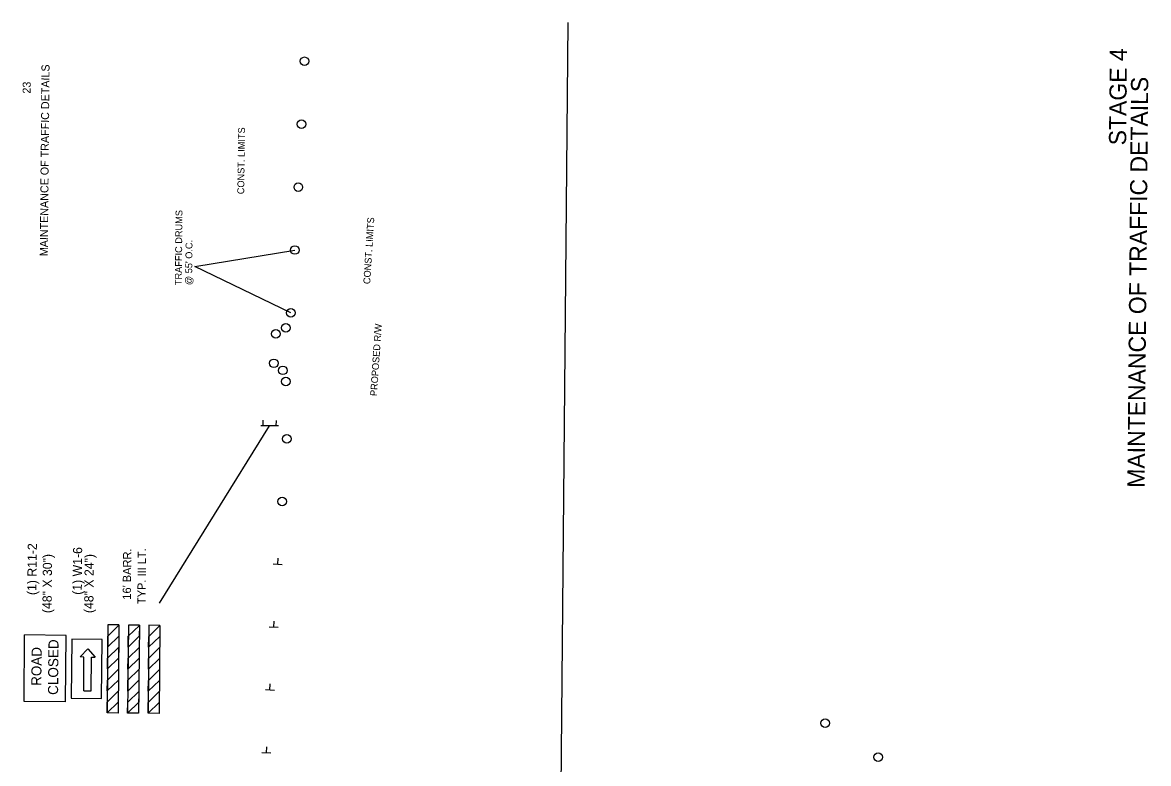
# Model space of a CAD drawing. Extents: x 1770269 to 1771406, y 724066 to 730989.
# Drawn here: x 1770316 to 1771298, y 730342 to 730989 of the extents above; entities that cross this region are included whole.
import ezdxf

# ---------------------------------------------------------------- set-up
doc = ezdxf.new("R2010")
doc.units = 0
for name, color, linetype in [('Default', 7, 'Continuous'), ('R_Border', 7, 'Continuous'), ('R_Border Notes', 7, 'Continuous'), ('R_Border PE', 7, 'Continuous'), ('R_Dimension', 7, 'Continuous'), ('R_MOT', 7, 'Continuous'), ('R_ROW Annot', 7, 'Continuous')]:
    doc.layers.add(name, color=color, linetype=linetype)

msp = doc.modelspace()

# ---------------------------------------------------------------- linework, layer by layer
at = {"layer": 'Default'}
for p, q in [((1770538.66, 730515.52), (1770539, 730520.85)), ((1770542.54, 730515.16), (1770534.73, 730515.66)), ((1770538.98, 730460.3), (1770531.17, 730460.75)), ((1770535.11, 730460.64), (1770535.42, 730465.97)), ((1770531.81, 730405.74), (1770532.1, 730411.07)), ((1770535.69, 730405.41), (1770527.88, 730405.83)), ((1770532.66, 730350.51), (1770524.85, 730350.9)), ((1770528.78, 730350.82), (1770529.05, 730356.15))]:
    msp.add_line(p, q, dxfattribs=at)
at = {"layer": 'R_Border Notes'}
msp.add_line((1770791.68, 730988.54), (1770777.32, 729407.71), dxfattribs=at)
at = {"layer": 'R_Border PE'}
msp.add_line((1770435.3, 730481.7), (1770531.55, 730636.47), dxfattribs=at)
at = {"layer": 'R_Dimension'}
msp.add_lwpolyline([(1770550.07, 730735.01), (1770466.33, 730775.45), (1770553.46, 730789.9)], dxfattribs=at)
at = {"layer": 'R_MOT'}
for p, q in [((1770539.34, 730636.42), (1770523.76, 730636.53)), ((1770525.88, 730636.51), (1770525.92, 730641.23)), ((1770537.37, 730636.43), (1770537.4, 730641.15)), ((1770390.38, 730462.64), (1770389.68, 730385.76)), ((1770400.03, 730462.55), (1770390.38, 730462.64)), ((1770400.03, 730462.55), (1770390.38, 730462.64)), ((1770400.03, 730462.55), (1770399.34, 730385.68)), ((1770408.28, 730462.47), (1770407.58, 730385.6)), ((1770417.9, 730462.39), (1770408.28, 730462.47)), ((1770417.9, 730462.39), (1770408.28, 730462.47)), ((1770417.9, 730462.39), (1770417.2, 730385.51)), ((1770426.11, 730462.31), (1770425.41, 730385.44)), ((1770435.73, 730462.22), (1770426.11, 730462.31)), ((1770435.73, 730462.22), (1770426.11, 730462.31)), ((1770435.73, 730462.22), (1770435.04, 730385.35)), ((1770317.21, 730395.88), (1770317.74, 730453.84)), ((1770353.94, 730453.51), (1770317.74, 730453.84)), ((1770353.42, 730395.55), (1770353.94, 730453.51)), ((1770366.27, 730434.61), (1770372.88, 730441.73)), ((1770372.88, 730441.73), (1770379.36, 730434.49)), ((1770369.54, 730434.58), (1770366.27, 730434.61)), ((1770369.27, 730405.19), (1770369.54, 730434.58)), ((1770375.82, 730405.13), (1770376.08, 730434.52)), ((1770376.08, 730434.52), (1770379.36, 730434.49)), ((1770369.27, 730405.19), (1770375.82, 730405.13)), ((1770353.42, 730395.55), (1770317.21, 730395.88)), ((1770399.34, 730385.68), (1770389.68, 730385.76)), ((1770399.31, 730385.73), (1770399.25, 730385.68)), ((1770417.2, 730385.51), (1770407.58, 730385.6)), ((1770417.2, 730385.51), (1770407.58, 730385.6)), ((1770435.04, 730385.35), (1770425.41, 730385.44))]:
    msp.add_line(p, q, dxfattribs=at)
for points in [[(1770390.21, 730443.39), (1770390.32, 730452.84), (1770400, 730462.35), (1770399.92, 730452.93)], [(1770408.1, 730443.23), (1770408.22, 730452.68), (1770417.9, 730462.19), (1770417.81, 730452.76)], [(1770425.94, 730443.07), (1770426.05, 730452.52), (1770435.73, 730462.02), (1770435.65, 730452.6)], [(1770358.91, 730450.25), (1770358.45, 730398.72), (1770384.8, 730398.48), (1770385.27, 730450.01)], [(1770390.03, 730424.18), (1770390.15, 730433.63), (1770399.83, 730443.14), (1770399.74, 730433.72)], [(1770407.93, 730424.02), (1770408.04, 730433.47), (1770417.72, 730442.98), (1770417.64, 730433.55)], [(1770425.76, 730423.86), (1770425.88, 730433.31), (1770435.56, 730442.81), (1770435.47, 730433.39)], [(1770389.86, 730404.97), (1770389.97, 730414.42), (1770399.66, 730423.93), (1770399.57, 730414.51)], [(1770407.75, 730404.81), (1770407.87, 730414.26), (1770417.55, 730423.77), (1770417.46, 730414.35)], [(1770425.59, 730404.65), (1770425.7, 730414.1), (1770435.38, 730423.61), (1770435.3, 730414.18)], [(1770389.68, 730385.76), (1770389.8, 730395.21), (1770399.48, 730404.72), (1770399.4, 730395.3)], [(1770407.58, 730385.6), (1770407.69, 730395.05), (1770417.37, 730404.56), (1770417.29, 730395.14)], [(1770425.41, 730385.44), (1770425.53, 730394.89), (1770435.21, 730404.4), (1770435.12, 730394.97)]]:
    msp.add_lwpolyline(points, close=True, dxfattribs=at)
for centre in [(1770562.04, 730954.68), (1770559.44, 730899.74), (1770556.58, 730844.81), (1770553.46, 730789.9), (1770550.07, 730735.01), (1770545.61, 730721.87), (1770536.97, 730716.84), (1770535.24, 730690.99), (1770543.14, 730684.85), (1770545.68, 730675.18), (1770546.51, 730625.13), (1770542.45, 730570.28), (1771016.24, 730376.77), (1771062.51, 730347.04)]:
    msp.add_circle(centre, 3.75, dxfattribs=at)

# ---------------------------------------------------------------- texts
at = {"layer": 'Default'}
for s, p in [('STAGE 4', (1771278.97, 730881.25)), ('MAINTENANCE OF TRAFFIC DETAILS', (1771295.03, 730582.27))]:
    msp.add_text(s, height=15, rotation=89.47959, dxfattribs=at).set_placement(p)
at = {"layer": 'R_Border'}
for s, p in [('MAINTENANCE OF TRAFFIC DETAILS', (1770337.97, 730784.47)), ('23', (1770322.99, 730926.44))]:
    msp.add_text(s, height=7, rotation=89.47959, dxfattribs=at).set_placement(p)
at = {"layer": 'R_Dimension'}
for s, rotation, p in [('CONST. LIMITS', 89.26419, (1770509.32, 730838.59)), ('TRAFFIC DRUMS', 89.47959, (1770454.88, 730759.27)), ('CONST. LIMITS', 86.41059, (1770619.24, 730760)), ("@ 55' O.C.", 89.47959, (1770463.88, 730759.19))]:
    msp.add_text(s, height=6, rotation=rotation, dxfattribs=at).set_placement(p)
at = {"layer": 'R_MOT'}
for s, height, p in [('(1) R11-2', 8.004, (1770328.02, 730488.64)), ('(1) W1-6', 8, (1770367.6, 730488.89)), ("16' BARR.", 7.204, (1770410.46, 730484.64)), ('TYP. III LT.', 7.2036, (1770423.29, 730480.78)), ('(48" X 30")', 8.004, (1770341.26, 730472.89)), ('(48" X 24")', 8, (1770377.7, 730472.89)), ('CLOSED', 8.817, (1770346.93, 730401.46)), ('ROAD', 8.774, (1770332.31, 730409.38))]:
    msp.add_text(s, height=height, rotation=89.47959, dxfattribs=at).set_placement(p)
at = {"layer": 'R_ROW Annot'}
msp.add_text('PROPOSED R/W', height=6, rotation=86.17567, dxfattribs=at).set_placement((1770625.24, 730662.25))

doc.saveas('drawing.dxf')
